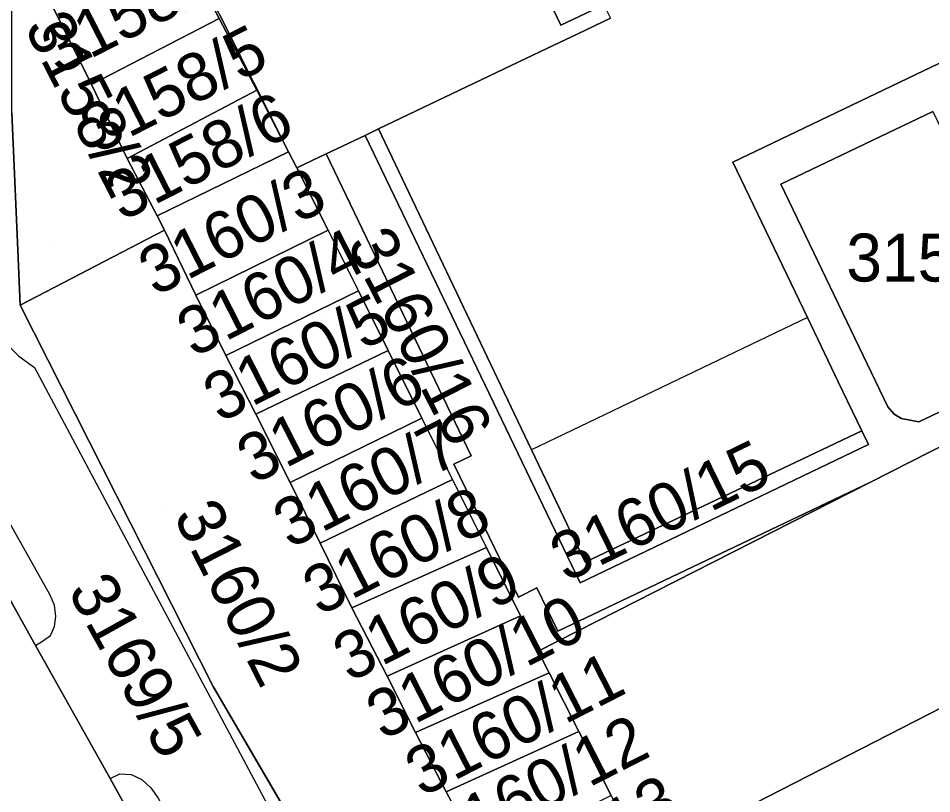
# Model space of a CAD drawing. Extents: x -264070 to -262271, y -1238894 to -1238141.
# Drawn here: x -263008.78 to -262970.7, y -1238499.49 to -1238467.13 of the extents above; entities that cross this region are included whole.
import ezdxf

# ---------------------------------------------------------------- set-up
doc = ezdxf.new("R2010")
doc.units = 0
for name, color, linetype in [('body_kn', 7, 'Continuous'), ('kladpar_druhypozemkov', 7, 'Continuous'), ('kladpar_hranice', 7, 'Continuous'), ('kladpar_parcelnecisla', 7, 'Continuous'), ('kladpar_plochy', 7, 'Continuous'), ('zappar_hrandruhpozemk', 7, 'Continuous')]:
    doc.layers.add(name, color=color, linetype=linetype)

msp = doc.modelspace()

# ---------------------------------------------------------------- linework, layer by layer
at = {"layer": 'body_kn'}
for p, q in [((-263000.41, -1238467.14), (-263000.41, -1238467.14)), ((-263000.41, -1238467.14), (-263000.41, -1238467.14)), ((-262986.16, -1238467.43), (-262986.16, -1238467.43)), ((-262985.45, -1238467.78), (-262985.45, -1238467.78)), ((-262986.48, -1238468.27), (-262986.48, -1238468.27)), ((-262987.33, -1238468.68), (-262987.33, -1238468.68)), ((-263005.73, -1238469.9), (-263005.73, -1238469.9)), ((-263005.73, -1238469.9), (-263005.73, -1238469.9)), ((-262998.84, -1238470.14), (-262998.84, -1238470.14)), ((-262998.84, -1238470.14), (-262998.84, -1238470.14)), ((-262994.32, -1238472.02), (-262994.32, -1238472.02)), ((-262993.76, -1238471.75), (-262993.76, -1238471.75)), ((-262997.51, -1238472.71), (-262997.51, -1238472.71)), ((-262997.51, -1238472.71), (-262997.51, -1238472.71)), ((-263004.24, -1238472.99), (-263004.24, -1238472.99)), ((-262997.34, -1238473.03), (-262997.34, -1238473.03)), ((-262995.94, -1238472.79), (-262995.94, -1238472.79)), ((-262978.99, -1238473.14), (-262978.99, -1238473.14)), ((-262997.16, -1238473.37), (-262997.16, -1238473.37)), ((-262976.99, -1238474.06), (-262976.99, -1238474.06)), ((-263002.99, -1238475.38), (-263002.99, -1238475.38)), ((-263002.68, -1238475.98), (-263002.68, -1238475.98)), ((-262995.86, -1238475.98), (-262995.86, -1238475.98)), ((-262995.86, -1238475.98), (-262995.86, -1238475.98)), ((-263001.38, -1238478.69), (-263001.38, -1238478.69)), ((-262994.6, -1238478.51), (-262994.6, -1238478.51)), ((-262994.6, -1238478.51), (-262994.6, -1238478.51)), ((-263008.7, -1238479.11), (-263008.7, -1238479.11)), ((-262975.88, -1238479.62), (-262975.88, -1238479.62)), ((-262975.88, -1238479.62), (-262975.88, -1238479.62)), ((-262993.36, -1238481), (-262993.36, -1238481)), ((-262993.36, -1238481), (-262993.36, -1238481)), ((-263008.76, -1238481.24), (-263008.76, -1238481.24)), ((-263000.13, -1238481.2), (-263000.13, -1238481.2)), ((-263008.1, -1238481.7), (-263008.1, -1238481.7)), ((-262974.59, -1238482.31), (-262974.59, -1238482.31)), ((-262972.52, -1238483.35), (-262972.52, -1238483.35)), ((-262998.87, -1238483.65), (-262998.87, -1238483.65)), ((-262998.87, -1238483.65), (-262998.87, -1238483.65)), ((-262991.95, -1238483.82), (-262991.95, -1238483.82)), ((-262991.95, -1238483.82), (-262991.95, -1238483.82)), ((-262972.26, -1238483.65), (-262972.26, -1238483.65)), ((-262971.96, -1238483.83), (-262971.96, -1238483.83)), ((-262971.23, -1238483.97), (-262971.23, -1238483.97)), ((-262973.61, -1238484.35), (-262973.61, -1238484.35)), ((-262973.61, -1238484.35), (-262973.61, -1238484.35)), ((-262973.33, -1238484.92), (-262973.33, -1238484.92)), ((-262987.38, -1238485.14), (-262987.38, -1238485.14)), ((-262989.9, -1238485.39), (-262989.9, -1238485.39)), ((-262990.62, -1238485.74), (-262990.62, -1238485.74)), ((-262990.68, -1238486.38), (-262990.68, -1238486.38)), ((-262990.68, -1238486.38), (-262990.68, -1238486.38)), ((-262997.44, -1238486.5), (-262997.44, -1238486.5)), ((-262973.27, -1238486.5), (-262973.27, -1238486.5)), ((-262996.2, -1238489.03), (-262996.2, -1238489.03)), ((-262989.26, -1238489.22), (-262989.26, -1238489.22)), ((-262989.26, -1238489.22), (-262989.26, -1238489.22)), ((-262985.15, -1238489.83), (-262985.15, -1238489.83)), ((-262985.15, -1238489.83), (-262985.15, -1238489.83)), ((-262987.16, -1238490.9), (-262987.16, -1238490.9)), ((-262985.36, -1238490.69), (-262985.36, -1238490.69)), ((-263007.46, -1238491.17), (-263007.46, -1238491.17)), ((-262987.92, -1238491.29), (-262987.92, -1238491.29)), ((-263007.27, -1238491.62), (-263007.27, -1238491.62)), ((-262994.87, -1238491.74), (-262994.87, -1238491.74)), ((-263007.21, -1238492.1), (-263007.21, -1238492.1)), ((-262987.84, -1238492.07), (-262987.84, -1238492.07)), ((-262987.84, -1238492.07), (-262987.84, -1238492.07)), ((-263007.27, -1238492.51), (-263007.27, -1238492.51)), ((-263007.44, -1238492.89), (-263007.44, -1238492.89)), ((-262986.29, -1238492.7), (-262986.29, -1238492.7)), ((-263008.06, -1238493.3), (-263008.06, -1238493.3)), ((-263008.06, -1238493.3), (-263008.06, -1238493.3)), ((-263007.77, -1238493.13), (-263007.77, -1238493.13)), ((-262987.11, -1238493.54), (-262987.11, -1238493.54)), ((-262987.11, -1238493.54), (-262987.11, -1238493.54)), ((-262986.65, -1238494.45), (-262986.65, -1238494.45)), ((-262986.65, -1238494.45), (-262986.65, -1238494.45)), ((-262993.4, -1238494.58), (-262993.4, -1238494.58)), ((-263000.65, -1238495.02), (-263000.65, -1238495.02)), ((-262992.22, -1238496.94), (-262992.22, -1238496.94)), ((-262985.41, -1238496.89), (-262985.41, -1238496.89)), ((-262985.41, -1238496.89), (-262985.41, -1238496.89)), ((-263004.55, -1238498.66), (-263004.55, -1238498.66)), ((-263004.95, -1238498.86), (-263004.95, -1238498.86)), ((-263004.95, -1238498.86), (-263004.95, -1238498.86)), ((-263004.07, -1238498.69), (-263004.07, -1238498.69)), ((-263003.63, -1238498.89), (-263003.63, -1238498.89)), ((-263003.26, -1238499.25), (-263003.26, -1238499.25)), ((-262990.94, -1238499.41), (-262990.94, -1238499.41))]:
    msp.add_line(p, q, dxfattribs=at)
at = {"layer": 'kladpar_druhypozemkov'}
for p, q in [((-263001.67, -1238468.34), (-263001.67, -1238468.34)), ((-263000.02, -1238471.34), (-263000.02, -1238471.34)), ((-262998.67, -1238473.95), (-262998.67, -1238473.95)), ((-262994.93, -1238476.57), (-262994.93, -1238476.57)), ((-263007.52, -1238476.64), (-263007.52, -1238476.64)), ((-262997.09, -1238477.08), (-262997.09, -1238477.08)), ((-262995.95, -1238479.59), (-262995.95, -1238479.59)), ((-262994.57, -1238482.19), (-262994.57, -1238482.19)), ((-262993.15, -1238484.99), (-262993.15, -1238484.99)), ((-262971.39, -1238485.14), (-262971.39, -1238485.14)), ((-262977.24, -1238486.7), (-262977.24, -1238486.7)), ((-263002.71, -1238487.5), (-263002.71, -1238487.5)), ((-262992.06, -1238487.57), (-262992.06, -1238487.57)), ((-262990.63, -1238490.35), (-262990.63, -1238490.35)), ((-262990.42, -1238493.84), (-262990.42, -1238493.84)), ((-263002.41, -1238495.2), (-263002.41, -1238495.2)), ((-262989.18, -1238496.13), (-262989.18, -1238496.13)), ((-262988.06, -1238498.7), (-262988.06, -1238498.7))]:
    msp.add_line(p, q, dxfattribs=at)
at = {"layer": 'kladpar_hranice'}
for points in [[(-262997.67, -1238459.64), (-262991.69, -1238456.65), (-262991.57, -1238456.59), (-262991.38, -1238456.5), (-262991.28, -1238456.69), (-262986.16, -1238467.43), (-262984.36, -1238466.57), (-262984.09, -1238467.13), (-262985.45, -1238467.78), (-262986.48, -1238468.27), (-262987.33, -1238468.68), (-262993.76, -1238471.75), (-262994.32, -1238472.02), (-262995.94, -1238472.79), (-262997.16, -1238473.37), (-262997.34, -1238473.03), (-262997.51, -1238472.71), (-263001.85, -1238464.06), (-262998.96, -1238462.59), (-262998.09, -1238461.48), (-262997.67, -1238460.19), (-262997.67, -1238459.64)], [(-262984.36, -1238466.57), (-262986.16, -1238467.43), (-262991.28, -1238456.69)], [(-262997.51, -1238472.71), (-262998.84, -1238470.14), (-263000.41, -1238467.14), (-263002.11, -1238463.87), (-263002.94, -1238462.27), (-262997.67, -1238459.64), (-262997.67, -1238460.19), (-262998.09, -1238461.48), (-262998.96, -1238462.59), (-263001.85, -1238464.06), (-262997.51, -1238472.71)], [(-263002.11, -1238463.87), (-263000.41, -1238467.14), (-263005.73, -1238469.9), (-263007.33, -1238466.68), (-263002.11, -1238463.87)], [(-263005.73, -1238469.9), (-263004.24, -1238472.99), (-263002.99, -1238475.38), (-263002.68, -1238475.98), (-263008.7, -1238479.11), (-263008.8, -1238476.81), (-263009.05, -1238471.08), (-263009.05, -1238466.83), (-263009.05, -1238465.35), (-263008.23, -1238464.93), (-263007.33, -1238466.68), (-263005.73, -1238469.9)], [(-262955.92, -1238465.25), (-262954.06, -1238469.16), (-262966.88, -1238475.48), (-262970.05, -1238468.86), (-262978.99, -1238473.14), (-262975.88, -1238479.62), (-262974.59, -1238482.31), (-262973.61, -1238484.35), (-262985.15, -1238489.83), (-262987.38, -1238485.14), (-262993.76, -1238471.75), (-262987.33, -1238468.68), (-262986.48, -1238468.27), (-262985.45, -1238467.78), (-262984.09, -1238467.13)], [(-262951.58, -1238472.83), (-262950.49, -1238474.92), (-262951.18, -1238475.27), (-262951.49, -1238474.6), (-262971.23, -1238483.97), (-262971.96, -1238483.83), (-262972.26, -1238483.65), (-262972.52, -1238483.35), (-262976.99, -1238474.06), (-262970.65, -1238471.02), (-262968.44, -1238475.6), (-262968, -1238475.92), (-262967.27, -1238476.05), (-262956.35, -1238470.8), (-262955.71, -1238472.14), (-262955.28, -1238472.46), (-262954.55, -1238472.6), (-262952.82, -1238471.78), (-262953.83, -1238469.59), (-262954.06, -1238469.16), (-262955.92, -1238465.25)], [(-263000.41, -1238467.14), (-262998.84, -1238470.14), (-263004.24, -1238472.99), (-263005.73, -1238469.9), (-263000.41, -1238467.14)], [(-262973.61, -1238484.35), (-262974.59, -1238482.31), (-262975.88, -1238479.62), (-262978.99, -1238473.14), (-262970.05, -1238468.86)], [(-262998.84, -1238470.14), (-262997.51, -1238472.71), (-263002.99, -1238475.38), (-263004.24, -1238472.99), (-262998.84, -1238470.14)], [(-263017.61, -1238527.12), (-263026.65, -1238510.12), (-263033.76, -1238496.15), (-263031.96, -1238488.46), (-263033.08, -1238486.01), (-263033.87, -1238484.27), (-263031.09, -1238482.85), (-263027.2, -1238480.85), (-263028.6, -1238478), (-263024.56, -1238476), (-263022.77, -1238479.62), (-263018.53, -1238477.57), (-263020.29, -1238473.89), (-263019.15, -1238473.32), (-263016.78, -1238472.15), (-263015.69, -1238471.61), (-263009.05, -1238471.08), (-263008.8, -1238476.81), (-263008.7, -1238479.11), (-263000.65, -1238495.02), (-262997.48, -1238500.45), (-262993.38, -1238507.47), (-262985.04, -1238522.41)], [(-262970.65, -1238471.02), (-262976.99, -1238474.06), (-262972.52, -1238483.35), (-262972.26, -1238483.65), (-262971.96, -1238483.83), (-262971.23, -1238483.97), (-262951.49, -1238474.6)], [(-262951.18, -1238475.27), (-262973.27, -1238486.5), (-262986.29, -1238492.7), (-262987.16, -1238490.9), (-262987.92, -1238491.29), (-262990.62, -1238485.74), (-262989.9, -1238485.39), (-262995.94, -1238472.79), (-262994.32, -1238472.02), (-262985.36, -1238490.69), (-262973.33, -1238484.92), (-262973.61, -1238484.35)], [(-262985.15, -1238489.83), (-262973.61, -1238484.35), (-262973.33, -1238484.92), (-262985.36, -1238490.69), (-262994.32, -1238472.02), (-262993.76, -1238471.75), (-262987.38, -1238485.14), (-262985.15, -1238489.83)], [(-262997.51, -1238472.71), (-262997.34, -1238473.03), (-262997.16, -1238473.37), (-262995.86, -1238475.98), (-263001.38, -1238478.69), (-263002.68, -1238475.98), (-263002.99, -1238475.38), (-262997.51, -1238472.71)], [(-262987.11, -1238493.54), (-262987.84, -1238492.07), (-262989.26, -1238489.22), (-262990.68, -1238486.38), (-262991.95, -1238483.82), (-262993.36, -1238481), (-262994.6, -1238478.51), (-262995.86, -1238475.98), (-262997.16, -1238473.37), (-262995.94, -1238472.79), (-262989.9, -1238485.39), (-262990.62, -1238485.74), (-262987.92, -1238491.29), (-262987.16, -1238490.9), (-262986.29, -1238492.7), (-262973.27, -1238486.5), (-262987.11, -1238493.54)], [(-262950.49, -1238474.92), (-262945.99, -1238483.66), (-262946.6, -1238483.96), (-262963.01, -1238492.17), (-262978.09, -1238499.9), (-262982.69, -1238502.27), (-262984.06, -1238499.56), (-262985.41, -1238496.89), (-262986.65, -1238494.45), (-262987.11, -1238493.54), (-262973.27, -1238486.5), (-262951.18, -1238475.27), (-262950.49, -1238474.92)], [(-262998.87, -1238483.65), (-262997.44, -1238486.5), (-262996.2, -1238489.03), (-262994.87, -1238491.74), (-262993.4, -1238494.58), (-262992.22, -1238496.94), (-262990.94, -1238499.41), (-262989.41, -1238502.28), (-262988.04, -1238504.92), (-262993.38, -1238507.47), (-262997.48, -1238500.45), (-263000.65, -1238495.02), (-263008.7, -1238479.11), (-263002.68, -1238475.98), (-263001.38, -1238478.69), (-263000.13, -1238481.2), (-262998.87, -1238483.65)], [(-262995.86, -1238475.98), (-262994.6, -1238478.51), (-263000.13, -1238481.2), (-263001.38, -1238478.69), (-262995.86, -1238475.98)], [(-262994.6, -1238478.51), (-262993.36, -1238481), (-262998.87, -1238483.65), (-263000.13, -1238481.2), (-262994.6, -1238478.51)], [(-262993.36, -1238481), (-262991.95, -1238483.82), (-262997.44, -1238486.5), (-262998.87, -1238483.65), (-262993.36, -1238481)], [(-262991.95, -1238483.82), (-262990.68, -1238486.38), (-262996.2, -1238489.03), (-262997.44, -1238486.5), (-262991.95, -1238483.82)], [(-262990.68, -1238486.38), (-262989.26, -1238489.22), (-262994.87, -1238491.74), (-262996.2, -1238489.03), (-262990.68, -1238486.38)], [(-263003.67, -1238501.16), (-263002.62, -1238500.56), (-263001.13, -1238503.17), (-263002.2, -1238503.78), (-263002.23, -1238503.72), (-263002.51, -1238503.23), (-263006.17, -1238505.35), (-263013.34, -1238509.49), (-263018.35, -1238512.39), (-263020.84, -1238507.95), (-263023.9, -1238502.48), (-263026.37, -1238498.08), (-263026.2, -1238497.99), (-263022.57, -1238495.9), (-263020.2, -1238494.54), (-263018.01, -1238493.28), (-263015.65, -1238491.92), (-263010.72, -1238489.09), (-263010.49, -1238488.95), (-263008.06, -1238493.3), (-263004.95, -1238498.86), (-263003.67, -1238501.16)], [(-262985.84, -1238536.62), (-263001.94, -1238508.22), (-263003.93, -1238509.31), (-263005, -1238507.42), (-263005.86, -1238505.89), (-263006.17, -1238505.35), (-263002.51, -1238503.23), (-263002.23, -1238503.72), (-263002.2, -1238503.78), (-263001.13, -1238503.17), (-263002.62, -1238500.56), (-263003.67, -1238501.16), (-263004.95, -1238498.86), (-263008.06, -1238493.3), (-263010.49, -1238488.95)], [(-262989.26, -1238489.22), (-262987.84, -1238492.07), (-262993.4, -1238494.58), (-262994.87, -1238491.74), (-262989.26, -1238489.22)], [(-262987.84, -1238492.07), (-262987.11, -1238493.54), (-262986.65, -1238494.45), (-262992.22, -1238496.94), (-262993.4, -1238494.58), (-262987.84, -1238492.07)], [(-262963.01, -1238492.17), (-262955.44, -1238506.52), (-262969.73, -1238514.26), (-262970.15, -1238514.49), (-262978.09, -1238499.9), (-262963.01, -1238492.17)], [(-262986.65, -1238494.45), (-262985.41, -1238496.89), (-262990.94, -1238499.41), (-262992.22, -1238496.94), (-262986.65, -1238494.45)], [(-262985.41, -1238496.89), (-262984.06, -1238499.56), (-262989.41, -1238502.28), (-262990.94, -1238499.41), (-262985.41, -1238496.89)]]:
    msp.add_lwpolyline(points, dxfattribs=at)
at = {"layer": 'kladpar_plochy'}
for p, q in [((-263008.8, -1238476.81), (-263008.7, -1238479.11)), ((-263008.7, -1238479.11), (-263000.65, -1238495.02)), ((-263008.06, -1238493.3), (-263010.49, -1238488.95)), ((-263004.95, -1238498.86), (-263008.06, -1238493.3)), ((-263000.65, -1238495.02), (-262997.48, -1238500.45)), ((-263003.67, -1238501.16), (-263004.95, -1238498.86))]:
    msp.add_line(p, q, dxfattribs=at)
for points in [[(-262997.67, -1238459.64), (-262991.69, -1238456.65), (-262991.57, -1238456.59), (-262991.38, -1238456.5), (-262991.28, -1238456.69), (-262986.16, -1238467.43), (-262984.36, -1238466.57), (-262984.09, -1238467.13), (-262985.45, -1238467.78), (-262986.48, -1238468.27), (-262987.33, -1238468.68), (-262993.76, -1238471.75), (-262994.32, -1238472.02), (-262995.94, -1238472.79), (-262997.16, -1238473.37), (-262997.34, -1238473.03), (-262997.51, -1238472.71), (-263001.85, -1238464.06), (-262998.96, -1238462.59), (-262998.09, -1238461.48), (-262997.67, -1238460.19)], [(-262997.51, -1238472.71), (-262998.84, -1238470.14), (-263000.41, -1238467.14), (-263002.11, -1238463.87), (-263002.94, -1238462.27), (-262997.67, -1238459.64), (-262997.67, -1238460.19), (-262998.09, -1238461.48), (-262998.96, -1238462.59), (-263001.85, -1238464.06)], [(-263002.11, -1238463.87), (-263000.41, -1238467.14), (-263005.73, -1238469.9), (-263007.33, -1238466.68)], [(-263005.73, -1238469.9), (-263004.24, -1238472.99), (-263002.99, -1238475.38), (-263002.68, -1238475.98), (-263008.7, -1238479.11), (-263008.8, -1238476.81), (-263009.05, -1238471.08), (-263009.05, -1238466.83), (-263009.05, -1238465.35), (-263008.23, -1238464.93), (-263007.33, -1238466.68)], [(-263000.41, -1238467.14), (-262998.84, -1238470.14), (-263004.24, -1238472.99), (-263005.73, -1238469.9)], [(-262998.84, -1238470.14), (-262997.51, -1238472.71), (-263002.99, -1238475.38), (-263004.24, -1238472.99)], [(-262985.15, -1238489.83), (-262973.61, -1238484.35), (-262973.33, -1238484.92), (-262985.36, -1238490.69), (-262994.32, -1238472.02), (-262993.76, -1238471.75), (-262987.38, -1238485.14)], [(-262997.51, -1238472.71), (-262997.34, -1238473.03), (-262997.16, -1238473.37), (-262995.86, -1238475.98), (-263001.38, -1238478.69), (-263002.68, -1238475.98), (-263002.99, -1238475.38)], [(-262987.11, -1238493.54), (-262987.84, -1238492.07), (-262989.26, -1238489.22), (-262990.68, -1238486.38), (-262991.95, -1238483.82), (-262993.36, -1238481), (-262994.6, -1238478.51), (-262995.86, -1238475.98), (-262997.16, -1238473.37), (-262995.94, -1238472.79), (-262989.9, -1238485.39), (-262990.62, -1238485.74), (-262987.92, -1238491.29), (-262987.16, -1238490.9), (-262986.29, -1238492.7), (-262973.27, -1238486.5)], [(-262950.49, -1238474.92), (-262945.99, -1238483.66), (-262946.6, -1238483.96), (-262963.01, -1238492.17), (-262978.09, -1238499.9), (-262982.69, -1238502.27), (-262984.06, -1238499.56), (-262985.41, -1238496.89), (-262986.65, -1238494.45), (-262987.11, -1238493.54), (-262973.27, -1238486.5), (-262951.18, -1238475.27)], [(-262998.87, -1238483.65), (-262997.44, -1238486.5), (-262996.2, -1238489.03), (-262994.87, -1238491.74), (-262993.4, -1238494.58), (-262992.22, -1238496.94), (-262990.94, -1238499.41), (-262989.41, -1238502.28), (-262988.04, -1238504.92), (-262993.38, -1238507.47), (-262997.48, -1238500.45), (-263000.65, -1238495.02), (-263008.7, -1238479.11), (-263002.68, -1238475.98), (-263001.38, -1238478.69), (-263000.13, -1238481.2)], [(-262995.86, -1238475.98), (-262994.6, -1238478.51), (-263000.13, -1238481.2), (-263001.38, -1238478.69)], [(-262994.6, -1238478.51), (-262993.36, -1238481), (-262998.87, -1238483.65), (-263000.13, -1238481.2)], [(-262993.36, -1238481), (-262991.95, -1238483.82), (-262997.44, -1238486.5), (-262998.87, -1238483.65)], [(-262991.95, -1238483.82), (-262990.68, -1238486.38), (-262996.2, -1238489.03), (-262997.44, -1238486.5)], [(-262990.68, -1238486.38), (-262989.26, -1238489.22), (-262994.87, -1238491.74), (-262996.2, -1238489.03)], [(-263003.67, -1238501.16), (-263002.62, -1238500.56), (-263001.13, -1238503.17), (-263002.2, -1238503.78), (-263002.23, -1238503.72), (-263002.51, -1238503.23), (-263006.17, -1238505.35), (-263013.34, -1238509.49), (-263018.35, -1238512.39), (-263020.84, -1238507.95), (-263023.9, -1238502.48), (-263026.37, -1238498.08), (-263026.2, -1238497.99), (-263022.57, -1238495.9), (-263020.2, -1238494.54), (-263018.01, -1238493.28), (-263015.65, -1238491.92), (-263010.72, -1238489.09), (-263010.49, -1238488.95), (-263008.06, -1238493.3), (-263004.95, -1238498.86)], [(-262989.26, -1238489.22), (-262987.84, -1238492.07), (-262993.4, -1238494.58), (-262994.87, -1238491.74)], [(-262987.84, -1238492.07), (-262987.11, -1238493.54), (-262986.65, -1238494.45), (-262992.22, -1238496.94), (-262993.4, -1238494.58)], [(-262963.01, -1238492.17), (-262955.44, -1238506.52), (-262969.73, -1238514.26), (-262970.15, -1238514.49), (-262978.09, -1238499.9)], [(-262986.65, -1238494.45), (-262985.41, -1238496.89), (-262990.94, -1238499.41), (-262992.22, -1238496.94)], [(-262985.41, -1238496.89), (-262984.06, -1238499.56), (-262989.41, -1238502.28), (-262990.94, -1238499.41)]]:
    msp.add_lwpolyline(points, close=True, dxfattribs=at)
for points in [[(-262984.36, -1238466.57), (-262986.16, -1238467.43), (-262991.28, -1238456.69)], [(-262957.3, -1238460.54), (-262953.6, -1238468.49), (-262953.1, -1238469.57), (-262951.58, -1238472.83), (-262950.49, -1238474.92), (-262951.18, -1238475.27), (-262951.49, -1238474.6), (-262971.23, -1238483.97), (-262971.96, -1238483.83), (-262972.26, -1238483.65), (-262972.52, -1238483.35), (-262976.99, -1238474.06), (-262970.65, -1238471.02), (-262968.44, -1238475.6), (-262968, -1238475.92), (-262967.27, -1238476.05), (-262956.35, -1238470.8), (-262955.71, -1238472.14), (-262955.28, -1238472.46), (-262954.55, -1238472.6), (-262952.82, -1238471.78), (-262953.83, -1238469.59), (-262954.06, -1238469.16), (-262955.92, -1238465.25)], [(-262955.92, -1238465.25), (-262954.06, -1238469.16), (-262966.88, -1238475.48), (-262970.05, -1238468.86), (-262978.99, -1238473.14), (-262975.88, -1238479.62), (-262974.59, -1238482.31), (-262973.61, -1238484.35), (-262985.15, -1238489.83), (-262987.38, -1238485.14), (-262993.76, -1238471.75), (-262987.33, -1238468.68), (-262986.48, -1238468.27), (-262985.45, -1238467.78), (-262984.09, -1238467.13)], [(-262951.18, -1238475.27), (-262973.27, -1238486.5), (-262986.29, -1238492.7), (-262987.16, -1238490.9), (-262987.92, -1238491.29), (-262990.62, -1238485.74), (-262989.9, -1238485.39), (-262995.94, -1238472.79), (-262994.32, -1238472.02), (-262985.36, -1238490.69), (-262973.33, -1238484.92), (-262973.61, -1238484.35), (-262974.59, -1238482.31), (-262975.88, -1238479.62), (-262978.99, -1238473.14), (-262970.05, -1238468.86)], [(-262970.65, -1238471.02), (-262976.99, -1238474.06), (-262972.52, -1238483.35), (-262972.26, -1238483.65), (-262971.96, -1238483.83), (-262971.23, -1238483.97), (-262951.49, -1238474.6)]]:
    msp.add_lwpolyline(points, dxfattribs=at)
at = {"layer": 'zappar_hrandruhpozemk'}
for p, q in [((-262975.88, -1238479.62), (-262987.38, -1238485.14)), ((-263008.1, -1238481.7), (-262993.82, -1238508.53))]:
    msp.add_line(p, q, dxfattribs=at)
for points in [[(-263009.43, -1238477.86), (-263009.51, -1238478.07), (-263009.63, -1238478.82), (-263009.8, -1238479.87), (-263009.4, -1238480.49), (-263009.11, -1238480.88), (-263008.76, -1238481.24), (-263008.1, -1238481.7)], [(-263008.06, -1238493.3), (-263007.77, -1238493.13), (-263007.44, -1238492.89), (-263007.27, -1238492.51), (-263007.21, -1238492.1), (-263007.27, -1238491.62), (-263007.46, -1238491.17), (-263011.36, -1238484.26), (-263011.74, -1238483.83), (-263012.21, -1238483.49), (-263012.68, -1238483.29), (-263013.18, -1238483.19), (-263014.2, -1238483.32), (-263015.18, -1238483.53), (-263016.09, -1238483.94), (-263017.74, -1238485.12)], [(-263004.95, -1238498.86), (-263004.55, -1238498.66), (-263004.07, -1238498.69), (-263003.63, -1238498.89), (-263003.26, -1238499.25), (-263002.95, -1238499.67), (-263002.81, -1238499.93)]]:
    msp.add_lwpolyline(points, dxfattribs=at)

# ---------------------------------------------------------------- texts
at = {"layer": 'kladpar_parcelnecisla'}
for s, rotation, p in [('3158/4', 27, (-263007.121, -1238469.523)), ('3158/2', 297, (-263008.552, -1238467.502)), ('3158/5', 27, (-263005.51, -1238472.818)), ('3158/6', 27, (-263004.451, -1238475.623)), ('3160/3', 27, (-263003.073, -1238478.754)), ('3160/4', 27, (-263001.472, -1238481.308)), ('3160/16', 297, (-262995.1, -1238476.53)), ('3160/5', 27, (-263000.371, -1238484.033)), ('3160/6', 27, (-262998.972, -1238486.598)), ('3160/7', 27, (-262997.46, -1238489.286)), ('3160/15', 26, (-262985.943, -1238490.684)), ('3160/8', 27, (-262996.223, -1238492.088)), ('3160/2', 297, (-263002.337, -1238487.891)), ('3160/9', 27, (-262994.962, -1238494.858)), ('3169/5', 299, (-263006.744, -1238491.023)), ('3160/10', 27, (-262993.578, -1238497.274)), ('3160/11', 27, (-262991.955, -1238499.644)), ('3160/12', 27, (-262990.947, -1238502.279)), ('3160/13', 29, (-262989.497, -1238505.037))]:
    msp.add_text(s, height=2, rotation=rotation, dxfattribs=at).set_placement(p)
msp.add_text('3159/1', height=2, dxfattribs=at).set_placement((-262974.259, -1238478.12))

doc.saveas('drawing.dxf')
